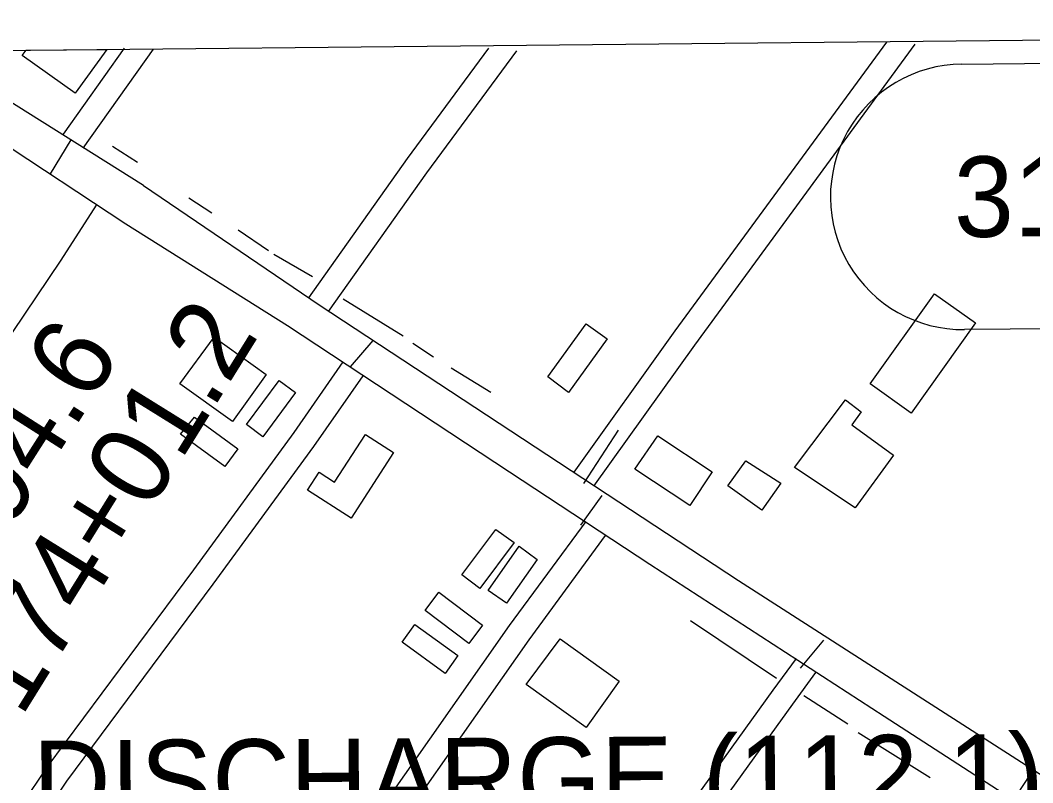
# Model space of a CAD drawing. Extents: x 3625074 to 3663148, y 511451 to 537151.
# Drawn here: x 3630641 to 3631899, y 534147 to 535095 of the extents above; entities that cross this region are included whole.
import ezdxf

# ---------------------------------------------------------------- set-up
doc = ezdxf.new("R2010")
doc.units = 0
for name, color, linetype in [('V-BLDG-OTLN', 7, 'Continuous'), ('V-CHAN-NAID', 7, 'Continuous'), ('V-GRID-FRAM', 7, 'Continuous'), ('V-ROAD-CNTR', 7, 'Continuous'), ('V-ROAD-IDEN', 7, 'Continuous'), ('V-SURV-IDEN', 7, 'Continuous'), ('V-TOPO-SHOR', 7, 'Continuous')]:
    doc.layers.add(name, color=color, linetype=linetype)

msp = doc.modelspace()

# ---------------------------------------------------------------- linework, layer by layer
at = {"layer": 'V-BLDG-OTLN'}
for p, q in [((3630644, 535050.7), (3630648.9, 535057.4)), ((3630709.6, 535003.9), (3630644, 535050.7)), ((3630648.9, 535057.4), (3630749, 535058.4)), ((3630749, 535058.4), (3630709.6, 535003.9))]:
    msp.add_line(p, q, dxfattribs=at)
for points in [[(3631828.5, 534718.7), (3631748.3, 534606.6), (3631697.4, 534643), (3631777.4, 534754.8)], [(3631296.8, 534651.7), (3631344.4, 534717.6), (3631370.8, 534698.6), (3631322.7, 534632)], [(3630882.6, 534700.8), (3630947, 534654.6), (3630905, 534596), (3630839.8, 534642.8)], [(3630963, 534647), (3630983.5, 534632), (3630942.9, 534577.1), (3630922.5, 534592.2)], [(3631678.7, 534488.9), (3631603.5, 534538.8), (3631666.7, 534623), (3631686.3, 534608), (3631674.8, 534592.1), (3631726.5, 534554.2)], [(3630858, 534601.5), (3630911.7, 534562.2), (3630895.7, 534540.3), (3630840.6, 534580.5)], [(3631070.5, 534579.8), (3631105.1, 534557.6), (3631052.8, 534475.8), (3630998.4, 534510.7), (3631012.7, 534533.1), (3631032, 534520.8)], [(3631405.2, 534536.9), (3631433.6, 534578.4), (3631501.3, 534533.4), (3631473.5, 534491.6)], [(3631520.7, 534516), (3631543, 534547), (3631586.5, 534519.2), (3631562.7, 534485.9)], [(3631232.4, 534461.8), (3631255.2, 534445.6), (3631212.6, 534388.7), (3631190.2, 534405.5)], [(3631261.4, 534441.1), (3631283.8, 534424.7), (3631245.8, 534370.2), (3631223, 534386)], [(3631144.6, 534361.3), (3631161.5, 534383.8), (3631215.9, 534342.8), (3631199, 534320.3)], [(3631131.8, 534343.9), (3631185.3, 534305.1), (3631169.3, 534283), (3631115.8, 534321.8)], [(3631312.4, 534325.8), (3631385.8, 534273.3), (3631344.7, 534215.7), (3631270.1, 534269)]]:
    msp.add_lwpolyline(points, close=True, dxfattribs=at)
at = {"layer": 'V-GRID-FRAM'}
msp.add_lwpolyline([(3629129.4, 535042.1), (3660791.6, 535359.9), (3660982, 517178), (3629304, 516860), (3629129.4, 535042.1)], dxfattribs=at)
at = {"layer": 'V-ROAD-CNTR'}
for p, q in [((3630704.2, 534946), (3630678.6, 534903.7)), ((3631079.5, 534696.9), (3631051.4, 534663.9)), ((3631341.5, 534518.8), (3631384.6, 534585.2)), ((3631363.9, 534504.1), (3631337.4, 534467)), ((3631639.5, 534324.3), (3631610.6, 534289.4)), ((3631895.9, 534156.9), (3631871.5, 534119.8))]:
    msp.add_line(p, q, dxfattribs=at)
for points in [[(3630770.6, 535059.9), (3630694.7, 534953)], [(3630999.9, 534749.9), (3631122.5, 534922.7), (3631223.7, 535060)], [(3631329.8, 534533.1), (3631455.3, 534708.6), (3631718.2, 535067.5)], [(3631354.2, 534515.7), (3631479.6, 534691), (3631753.4, 535064.9)], [(3630448.2, 535055.4), (3630772.8, 534841.6)], [(3630794.8, 534889.3), (3630589, 535018.1), (3630531.7, 535056.2)], [(3630806.7, 535058.9), (3630719.2, 534935.6)], [(3631024.4, 534732.6), (3631146.8, 534905.1), (3631258.6, 535056.7)], [(3630794.8, 534889.3), (3631012.7, 534740.9), (3631533.9, 534398.3), (3632035.9, 534076), (3632223.9, 533952.9), (3632498.3, 533771.5), (3632544.6, 533741.7), (3632585.8, 533709.9), (3632636.4, 533664.9), (3632687.2, 533616.9), (3632771.6, 533500.7), (3632901.2, 533307.7), (3633097.2, 533008), (3633444.7, 532500.1), (3633673.9, 532162.2), (3633780.9, 531985.9)], [(3630735.6, 534865), (3630691.9, 534796.7), (3630631.5, 534706.5), (3630555.7, 534589.9), (3630417.1, 534377)], [(3630772.8, 534841.6), (3630973.5, 534715.2), (3631249.4, 534533.4), (3631423.8, 534418.9), (3631714.9, 534229.7), (3632030.5, 534025.6), (3632185.5, 533923.4), (3632466.7, 533740.1), (3632562.9, 533672.1), (3632638.9, 533602), (3632761.3, 533443.4), (3632883.2, 533254.4), (3632974.7, 533112), (3633067.8, 532968.2), (3633219.4, 532738.8), (3633370, 532525.6), (3633514.4, 532324.7), (3633679.9, 532075.4), (3633970, 531601.1)], [(3631388.4, 533473.4), (3631326.8, 533519.4), (3630942.3, 533789.2), (3630813.5, 533869.6), (3630631.2, 534016.6), (3630614.2, 534042.1), (3630617.5, 534073.8), (3630626.4, 534096.9), (3630643.7, 534119.9), (3630675, 534166.4), (3630857.1, 534411.5), (3630981.9, 534582.3), (3631042.7, 534670)], [(3630898, 533852.2), (3630831, 533894.1), (3630653.6, 534037.1), (3630645.2, 534049.7), (3630646.9, 534066.7), (3630652.9, 534082.2), (3630668.2, 534102.5), (3630699.5, 534149.1), (3630881.3, 534393.8), (3631006.3, 534564.9), (3631067.4, 534652.9)], [(3630898, 533852.2), (3631020.3, 534015.8), (3631249.5, 534342.4), (3631344.4, 534471.9)], [(3630923.6, 533836.3), (3631044.6, 533998.2), (3631273.9, 534324.9), (3631368.6, 534454.2)], [(3631151.9, 533678.8), (3631201, 533742.7), (3631340.3, 533933.4), (3631577.1, 534262.2), (3631605.9, 534301.6)], [(3631176.5, 533661.5), (3631225, 533724.7), (3631364.5, 533915.8), (3631601.4, 534244.6), (3631630.1, 534283.9)]]:
    msp.add_lwpolyline(points, dxfattribs=at)
at = {"layer": 'V-ROAD-IDEN'}
for p, q in [((3631811.5, 535040.2), (3632141.5, 535043.5)), ((3631811.5, 535040.2), (3632141.5, 535043.5)), ((3631811.5, 535040.2), (3631811.5, 535040.2)), ((3632144.8, 534713.6), (3631814.8, 534710.2)), ((3632144.8, 534713.6), (3631814.8, 534710.2))]:
    msp.add_line(p, q, dxfattribs=at)
msp.add_arc((3631813.1, 534875.2), 165, 90.5751, 270.5751, dxfattribs=at)
msp.add_arc((3631813.1, 534875.2), 165, 90.5751, 270.5751, dxfattribs=at)
at = {"layer": 'V-TOPO-SHOR'}
for p, q in [((3630756, 534938.4), (3630787.3, 534918.2)), ((3630850.8, 534873.8), (3630879.6, 534855.2)), ((3630912.4, 534834.1), (3630950, 534808.5)), ((3630956.6, 534803.8), (3631004.7, 534776.3)), ((3631042.8, 534748.6), (3631117.2, 534702.5)), ((3631129.4, 534693.2), (3631155.1, 534676.3)), ((3631177, 534662.6), (3631226.2, 534632.7)), ((3631474.1, 534348.9), (3631581, 534277.1)), ((3631614.9, 534255.6), (3631669.6, 534220.1)), ((3631682.5, 534209.6), (3631772.2, 534153.5))]:
    msp.add_line(p, q, dxfattribs=at)

# ---------------------------------------------------------------- texts
at = {"layer": 'V-CHAN-NAID'}
msp.add_text('EAST JEFFERSON DISCHARGE (112.1) (2)', height=100, rotation=0.3854, dxfattribs=at).set_placement((3629438.9, 534091.1))
at = {"layer": 'V-ROAD-IDEN'}
msp.add_text('3155', height=100, rotation=0.5751, dxfattribs=at).set_placement((3631801.9, 534825.1))
at = {"layer": 'V-SURV-IDEN'}
for s, rotation, p in [('174+01.2', 58.1467, (3630642.6, 534227.1)), ('170+94.6', 57.4851, (3630465.8, 534205.8))]:
    msp.add_text(s, height=100, rotation=rotation, dxfattribs=at).set_placement(p)

doc.saveas('drawing.dxf')
